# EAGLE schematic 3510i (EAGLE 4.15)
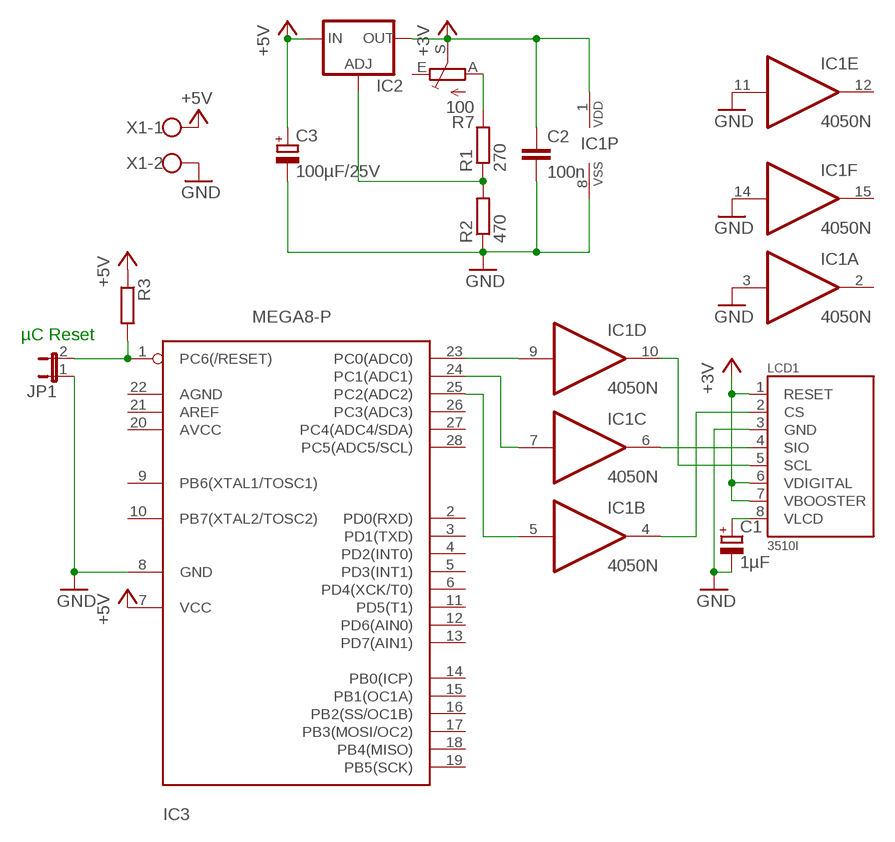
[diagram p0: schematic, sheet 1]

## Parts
C1  1µF  CPOL-EUE1.8-4  [E1,8-4]
C2  100n  C-EU025-024X044  [C025-024X044]
C3  100µF/25V  CPOL-EUE1.8-4  [E1,8-4]
IC1  4050N  [DIL16]
IC2  LM317TS  [317TS]
IC3  MEGA8-P  [DIL28-3]
JP1  JP1E  [JP1]
LCD1  3510I  [FE08-1]
R1  270  R-EU_0204/2V  [0204V]
R2  470  R-EU_0204/7  [0204/7]
R3  R-EU_0204/7  [0204/7]
R7  100  TRIM_EU-LI10  [LI10]
X1  W237-02P  [W237-132]

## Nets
+3V3: C2.1 IC1.1(P:VDD) IC2.2(OUT) LCD1.1(RESET) LCD1.6(VDIGITAL) LCD1.7(VBOOSTER) R7.S ; supply symbol labelled +3V
+5V: C3.+ IC2.3(IN) IC3.7(VCC) R3.1 X1.1
GND: C1.- C2.2 C3.- IC1.3(A:I) IC1.8(P:VSS) IC1.11(E:I) IC1.14(F:I) IC3.8(GND) JP1.1 LCD1.3(GND) R2.1 X1.2
N$1: IC3.1(PC6(/RESET)) JP1.2 R3.2
N$2: IC1.4(B:O) LCD1.2(CS)
N$3: IC1.6(C:O) LCD1.4(SIO)
N$4: IC1.10(D:O) LCD1.5(SCL)
N$5: C1.+ LCD1.8(VLCD)
N$6: R1.2 R7.A
N$8: IC1.5(B:I) IC3.25(PC2(ADC2))
N$9: IC1.7(C:I) IC3.24(PC1(ADC1))
N$10: IC1.9(D:I) IC3.23(PC0(ADC0))
N$13: IC2.1(ADJ) R1.1 R2.2
Unconnected: IC1.2(A:O) IC1.12(E:O) IC1.15(F:O) IC3.2(PD0(RXD)) IC3.3(PD1(TXD)) IC3.4(PD2(INT0)) IC3.5(PD3(INT1)) IC3.6(PD4(XCK/T0)) IC3.9(PB6(XTAL1/TOSC1)) IC3.10(PB7(XTAL2/TOSC2)) IC3.11(PD5(T1)) IC3.12(PD6(AIN0)) IC3.13(PD7(AIN1)) IC3.14(PB0(ICP)) IC3.15(PB1(OC1A)) IC3.16(PB2(SS/OC1B)) IC3.17(PB3(MOSI/OC2)) IC3.18(PB4(MISO)) IC3.19(PB5(SCK)) IC3.20(AVCC) IC3.21(AREF) IC3.22(AGND) IC3.26(PC3(ADC3)) IC3.27(PC4(ADC4/SDA)) IC3.28(PC5(ADC5/SCL)) R7.E

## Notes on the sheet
- µC Reset

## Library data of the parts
C1 C3 = rcl:CPOL-EU: POLARIZED CAPACITOR, European symbol
C2 = rcl:C-EU: CAPACITOR, European symbol
IC1 = 40xx:4050: Hex non-inverting BUFFER
IC2 = v-reg:LM317TS: VOLTAGE REGULATOR
IC3 = avr:MEGA8-P: MICROCONTROLLER 8 Kbytes FLASH 1 kbytes SRAM 512 bytes EEPROM USART 4-channel 10 bit ADC 2-channel 8 bit ADC
JP1 = jumper:JP1E: JUMPER
LCD1 = Nokia-LCDs (farb):3510I
R1-R3 = rcl:R-EU_: RESISTOR, European symbol
R7 = pot:TRIM_EU-: POTENTIOMETER
X1 = con-wago-508:W237-02P: WAGO SREW CLAMP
